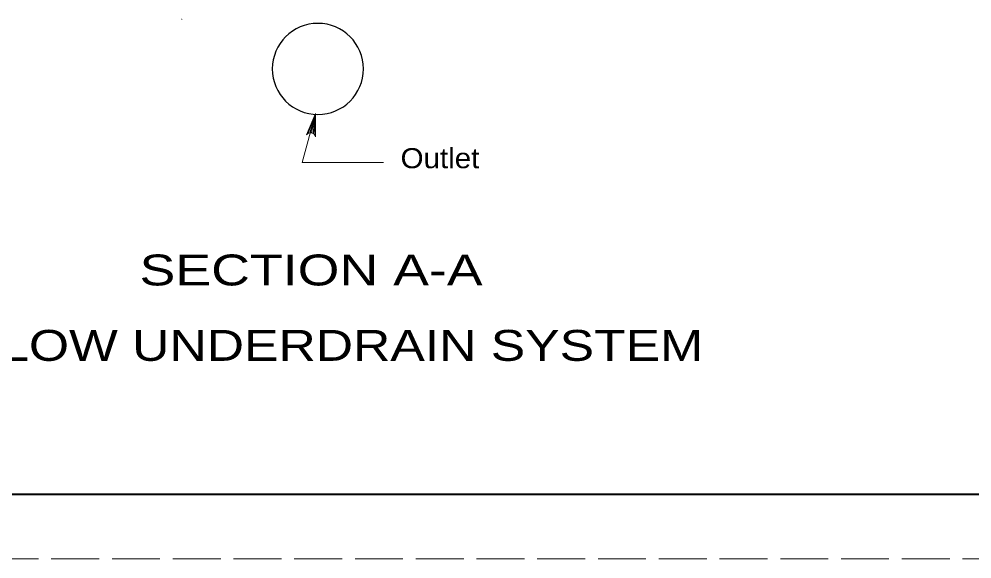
# Model space of a CAD drawing. Extents: x 743.9 to 777.9, y 1051 to 1073.
# Drawn here: x 749.75 to 757.15, y 1051.02 to 1055.21 of the extents above; entities that cross this region are included whole.
import ezdxf
from ezdxf.enums import TextEntityAlignment as Align

# ---------------------------------------------------------------- set-up
doc = ezdxf.new("R2010")
doc.units = 0
doc.header["$LTSCALE"] = 0.062
doc.linetypes.add('LONG_DASHED', pattern=[7.5, 6, -1.5])
doc.layers.add('1', color=7, linetype='Continuous', lineweight=13)

msp = doc.modelspace()

# ---------------------------------------------------------------- linework, layer by layer
at = {"layer": '1'}
for p in [(751.9955, 1054.32417), (752.00692, 1054.32817), (752.02158, 1054.32817), (752.03233, 1054.32425), (752.04217, 1054.31675)]:
    msp.add_line(p, (752.05167, 1054.47833), dxfattribs=at)
at = {"layer": '1', "linetype": 'LONG_DASHED'}
msp.add_lwpolyline([(743.86317, 1051.01808), (777.86317, 1051.01808), (777.86317, 1073.01808), (743.86317, 1073.01808)], close=True, dxfattribs=at)
at = {"layer": '1', "lineweight": 25}
msp.add_lwpolyline([(777.36317, 1051.51808), (745.86317, 1051.51808), (745.86317, 1072.51808)], dxfattribs=at)
at = {"layer": '1', "lineweight": 40}
msp.add_lwpolyline([(745.86317, 1072.51808), (777.36317, 1072.51808), (777.36317, 1051.51808), (745.86317, 1051.51808)], close=True, dxfattribs=at)
msp.add_lwpolyline([(745.86317, 1072.51808), (777.36317, 1072.51808), (777.36317, 1051.51808), (745.86317, 1051.51808)], close=True, dxfattribs=at)
at = {"layer": '1'}
for points in [[(752.05167, 1054.47833), (751.94733, 1054.09858), (752.57933, 1054.09858)], [(751.98217, 1054.31175), (752.05167, 1054.47833), (752.05158, 1054.29783)]]:
    msp.add_lwpolyline(points, dxfattribs=at)
for centre, radius, start, end in [((43.04098, 111.4838), 1179.76402, 53.12311, 53.12334), ((752.0141, 1054.29074), 0.0382, 10.75848, 146.58461)]:
    msp.add_arc(centre, radius, start, end, dxfattribs=at)
at = {"layer": '1', "lineweight": 25}
for start, end in [(0, 180), (180, 0)]:
    msp.add_arc((752.07009, 1054.82427), 0.35399, start, end, dxfattribs=at)

# ---------------------------------------------------------------- texts
at = {"layer": '1'}
for s, height, width, p in [('Outlet', 0.156, 1.1, (752.71275, 1054.05292)), ('SECTION A-A', 0.24, 1.3, (750.68458, 1053.14242))]:
    msp.add_text(s, height=height, dxfattribs=dict(at, width=width)).set_placement(p)
at = {"layer": '1', "width": 1.25}
msp.add_text('SHALLOW UNDERDRAIN SYSTEM', height=0.24, dxfattribs=at).set_placement((751.8085, 1052.55675), align=Align.CENTER)

doc.saveas('drawing.dxf')
